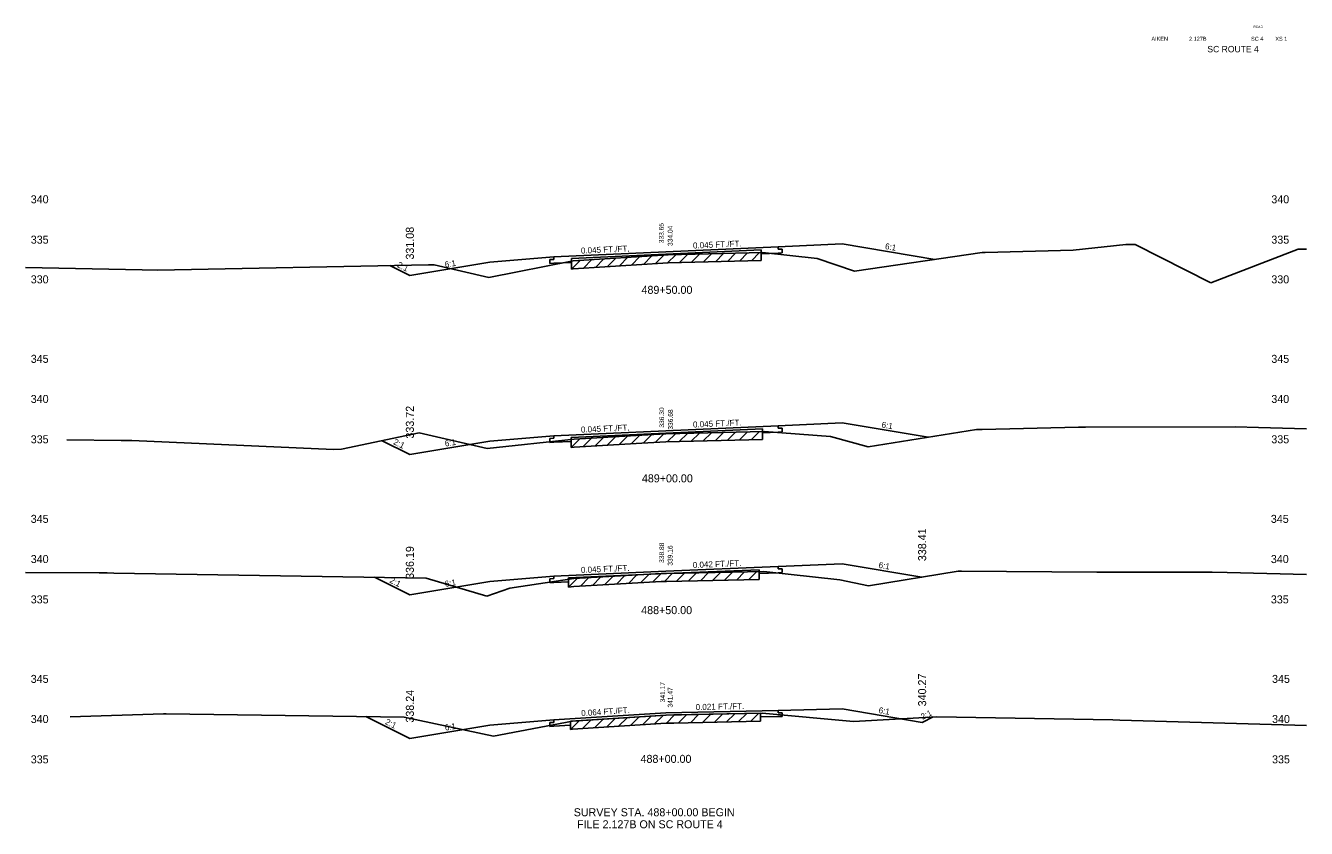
# Model space of a CAD drawing. Extents: x 883 to 1160, y 1002 to 4323.
# Drawn here: x 1000 to 1160, y 1002 to 1102.3 of the extents above; entities that cross this region are included whole.
import ezdxf

# ---------------------------------------------------------------- set-up
doc = ezdxf.new("R2010")
doc.units = 0
for name, color, linetype in [('Level 1', 7, 'Continuous'), ('Level 10', 7, 'Continuous'), ('Level 11', 7, 'Continuous'), ('Level 12', 7, 'Continuous'), ('Level 3', 7, 'Continuous'), ('Level 32', 7, 'Continuous'), ('Level 33', 7, 'Continuous'), ('Level 53', 7, 'Continuous'), ('Level 59', 7, 'Continuous'), ('Level 6', 7, 'Continuous'), ('Level 60', 7, 'Continuous'), ('Level 61', 7, 'Continuous'), ('Level 7', 7, 'Continuous')]:
    doc.layers.add(name, color=color, linetype=linetype)

msp = doc.modelspace()

# ---------------------------------------------------------------- linework, layer by layer
at = {"layer": 'Level 11'}
for p, q in [((1094, 1074.37), (1094, 1074.67)), ((1094.5, 1074.4), (1094, 1074.37)), ((1094, 1073.89), (1094.5, 1073.92)), ((1094.5, 1073.92), (1094.5, 1074.4)), ((1066, 1073.11), (1065.5, 1073.09)), ((1065.5, 1073.09), (1065.5, 1072.61)), ((1065.5, 1072.61), (1066, 1072.63)), ((1066, 1073.41), (1066, 1073.11)), ((1094, 1052.01), (1094, 1052.31)), ((1094.5, 1052.03), (1094, 1052.01)), ((1094, 1051.53), (1094.5, 1051.55)), ((1094.5, 1051.55), (1094.5, 1052.03)), ((1066, 1050.75), (1065.5, 1050.73)), ((1065.5, 1050.73), (1065.5, 1050.25)), ((1065.5, 1050.25), (1066, 1050.27)), ((1066, 1051.05), (1066, 1050.75)), ((1094, 1034.44), (1094, 1034.74)), ((1094.5, 1034.46), (1094, 1034.44)), ((1094, 1033.96), (1094.5, 1033.98)), ((1094.5, 1033.98), (1094.5, 1034.46)), ((1066, 1033.23), (1065.5, 1033.21)), ((1065.5, 1033.21), (1065.5, 1032.73)), ((1065.5, 1032.73), (1066, 1032.75)), ((1066, 1033.53), (1066, 1033.23)), ((1094, 1016.47), (1094, 1016.77)), ((1094.5, 1016.48), (1094, 1016.47)), ((1094.5, 1016), (1094.5, 1016.48)), ((1066, 1015.27), (1065.5, 1015.24)), ((1065.5, 1015.24), (1065.5, 1014.76)), ((1065.5, 1014.76), (1066, 1014.79)), ((1066, 1015.57), (1066, 1015.27)), ((1094, 1015.99), (1094.5, 1016))]:
    msp.add_line(p, q, dxfattribs=at)
at = {"layer": 'Level 12'}
for p, q in [((1091.9, 1073.95), (1091.9, 1073.8)), ((1091.9, 1073.8), (1094, 1073.89)), ((1068.18, 1072.73), (1066, 1072.63)), ((1068.18, 1072.88), (1068.18, 1072.73)), ((1092.07, 1051.6), (1092.07, 1051.45)), ((1092.07, 1051.45), (1094, 1051.53)), ((1068.14, 1050.37), (1066, 1050.27)), ((1068.14, 1050.62), (1068.14, 1050.37)), ((1091.64, 1034.1), (1091.64, 1033.86)), ((1091.64, 1033.86), (1094, 1033.96)), ((1067.8, 1032.83), (1066, 1032.75)), ((1067.8, 1033.14), (1067.8, 1032.83)), ((1091.8, 1016.42), (1091.8, 1015.94)), ((1068.06, 1014.92), (1066, 1014.79)), ((1068.06, 1015.37), (1068.06, 1014.92)), ((1091.8, 1015.94), (1094, 1015.99))]:
    msp.add_line(p, q, dxfattribs=at)
at = {"layer": 'Level 53'}
for p, q in [((1080, 1073.74), (1068.18, 1073.21)), ((1080, 1073.74), (1091.9, 1074.28)), ((1091.9, 1074.28), (1091.9, 1073.95)), ((1068.18, 1073.21), (1068.18, 1072.88)), ((1080, 1051.38), (1068.14, 1050.85)), ((1080, 1051.38), (1092.07, 1051.93)), ((1092.07, 1051.93), (1092.07, 1051.6)), ((1068.14, 1050.85), (1068.14, 1050.62)), ((1080, 1033.86), (1067.8, 1033.31)), ((1080, 1033.86), (1091.64, 1034.34)), ((1091.64, 1034.34), (1091.64, 1034.1)), ((1067.8, 1033.31), (1067.8, 1033.14)), ((1080, 1016.17), (1068.06, 1015.4)), ((1080, 1016.17), (1091.8, 1016.42)), ((1091.8, 1016.42), (1091.8, 1016.42)), ((1068.06, 1015.4), (1068.06, 1015.37))]:
    msp.add_line(p, q, dxfattribs=at)
at = {"layer": 'Level 59'}
for p, q in [((1066, 1073.41), (1080, 1074.04)), ((1080, 1074.04), (1094, 1074.67)), ((1066, 1051.05), (1080, 1051.68)), ((1080, 1051.68), (1094, 1052.31)), ((1066, 1033.53), (1080, 1034.16)), ((1080, 1034.16), (1094, 1034.74)), ((1066, 1015.57), (1080, 1016.47)), ((1080, 1016.47), (1094, 1016.77))]:
    msp.add_line(p, q, dxfattribs=at)
at = {"layer": 'Level 6'}
for p, q in [((1094, 1074.67), (1102, 1075.03)), ((1058, 1072.75), (1066, 1073.41)), ((1094, 1052.31), (1102, 1052.67)), ((1058, 1050.39), (1066, 1051.05)), ((1094, 1034.74), (1102, 1035.08)), ((1058, 1032.86), (1066, 1033.53)), ((1094, 1016.77), (1102, 1016.94)), ((1058, 1014.9), (1066, 1015.57))]:
    msp.add_line(p, q, dxfattribs=at)
at = {"layer": 'Level 60'}
for p, q in [((1068.41, 1072.93), (1080.29, 1073.67)), ((1080.29, 1073.67), (1092.06, 1073.96)), ((1092.06, 1073.96), (1098.88, 1073.21)), ((1103.53, 1071.62), (1119.5, 1073.97)), ((1119.5, 1073.97), (1119.88, 1073.98)), ((1119.88, 1073.98), (1130.88, 1074.27)), ((1130.88, 1074.27), (1137.46, 1074.96)), ((1137.46, 1074.96), (1138.63, 1074.96)), ((1138.63, 1074.96), (1148.06, 1070.18)), ((1148.06, 1070.18), (1158.99, 1074.39)), ((1158.99, 1074.39), (1160, 1074.36)), ((1000, 1072.07), (1014.57, 1071.79)), ((1016.48, 1071.76), (1050.35, 1072.42)), ((1050.35, 1072.42), (1051.02, 1072.42)), ((1051.02, 1072.42), (1057.88, 1070.83)), ((1057.88, 1070.83), (1068.41, 1072.93)), ((1098.88, 1073.21), (1103.53, 1071.62)), ((1014.57, 1071.79), (1016.48, 1071.76)), ((1039.46, 1049.38), (1049.17, 1051.44)), ((1049.17, 1051.44), (1057.66, 1049.49)), ((1076.98, 1051.13), (1080, 1051.3)), ((1080, 1051.3), (1092.26, 1051.61)), ((1092.26, 1051.61), (1100.56, 1050.99)), ((1105.24, 1049.67), (1118.81, 1051.87)), ((1118.81, 1051.87), (1119.51, 1051.86)), ((1119.51, 1051.86), (1131.54, 1052.15)), ((1131.54, 1052.15), (1132.39, 1052.15)), ((1132.39, 1052.15), (1151.14, 1052.2)), ((1151.14, 1052.2), (1154, 1052.12)), ((1154, 1052.12), (1160, 1051.93)), ((1005.15, 1050.56), (1011.95, 1050.48)), ((1011.95, 1050.48), (1013.27, 1050.46)), ((1013.27, 1050.46), (1038.46, 1049.36)), ((1057.66, 1049.49), (1068.54, 1050.66)), ((1068.54, 1050.66), (1076.98, 1051.13)), ((1100.56, 1050.99), (1105.24, 1049.67)), ((1038.46, 1049.36), (1039.46, 1049.38)), ((1000, 1034), (1009.19, 1033.94)), ((1009.19, 1033.94), (1010.17, 1033.93)), ((1010.17, 1033.93), (1011, 1033.89)), ((1011, 1033.89), (1050.05, 1033.3)), ((1068.49, 1033.25), (1079.41, 1033.85)), ((1079.41, 1033.85), (1080.05, 1033.88)), ((1080.05, 1033.88), (1092.22, 1034.11)), ((1092.22, 1034.11), (1101.71, 1033.07)), ((1105.31, 1032.33), (1116.48, 1034.17)), ((1116.48, 1034.17), (1116.92, 1034.16)), ((1116.92, 1034.16), (1133.84, 1034.04)), ((1133.84, 1034.04), (1148.22, 1034.05)), ((1148.22, 1034.05), (1150.1, 1034)), ((1150.1, 1034), (1160, 1033.73)), ((1050.05, 1033.3), (1057.63, 1031.04)), ((1057.63, 1031.04), (1060.51, 1032.02)), ((1060.51, 1032.02), (1068.49, 1033.25)), ((1101.71, 1033.07), (1105.31, 1032.33)), ((1005.55, 1015.94), (1017.22, 1016.32)), ((1017.22, 1016.32), (1017.55, 1016.32)), ((1017.55, 1016.32), (1047.3, 1015.92)), ((1068.32, 1015.41), (1080.04, 1016.17)), ((1080.04, 1016.17), (1080.96, 1016.19)), ((1080.96, 1016.19), (1092.01, 1016.42)), ((1092.01, 1016.42), (1103.44, 1015.36)), ((1047.3, 1015.92), (1058.43, 1013.56)), ((1058.43, 1013.56), (1068.32, 1015.41)), ((1103.44, 1015.36), (1113.84, 1015.98)), ((1113.84, 1015.98), (1135.82, 1015.57)), ((1135.82, 1015.57), (1136.7, 1015.53)), ((1136.7, 1015.53), (1160, 1014.87))]:
    msp.add_line(p, q, dxfattribs=at)
at = {"layer": 'Level 61'}
for p, q in [((1079.74, 1073.64), (1078.68, 1072.57)), ((1081.21, 1073.69), (1080.18, 1072.66)), ((1082.7, 1073.73), (1081.68, 1072.7)), ((1084.2, 1073.77), (1083.18, 1072.74)), ((1085.7, 1073.8), (1084.68, 1072.78)), ((1087.2, 1073.84), (1086.18, 1072.81)), ((1088.7, 1073.88), (1087.68, 1072.85)), ((1090.2, 1073.91), (1089.18, 1072.89)), ((1091.7, 1073.95), (1090.68, 1072.92)), ((1091.9, 1072.95), (1091.9, 1073.95)), ((1069.28, 1072.98), (1068.18, 1071.88)), ((1068.18, 1072.88), (1068.18, 1071.88)), ((1068.41, 1071.93), (1080.29, 1072.67)), ((1070.74, 1073.08), (1069.68, 1072.01)), ((1072.24, 1073.17), (1071.18, 1072.1)), ((1073.74, 1073.26), (1072.68, 1072.2)), ((1075.24, 1073.36), (1074.18, 1072.29)), ((1076.74, 1073.45), (1075.68, 1072.38)), ((1078.24, 1073.54), (1077.18, 1072.48)), ((1080.29, 1072.67), (1091.9, 1072.95)), ((1068.18, 1071.88), (1068.41, 1071.93)), ((1079.7, 1051.28), (1078.64, 1050.22)), ((1081.17, 1051.33), (1080.14, 1050.3)), ((1082.67, 1051.37), (1081.64, 1050.34)), ((1084.17, 1051.4), (1083.14, 1050.38)), ((1085.67, 1051.44), (1084.64, 1050.42)), ((1087.17, 1051.48), (1086.14, 1050.45)), ((1088.67, 1051.52), (1087.64, 1050.49)), ((1090.17, 1051.56), (1089.14, 1050.53)), ((1091.67, 1051.59), (1090.64, 1050.57)), ((1092.07, 1050.6), (1092.07, 1051.6)), ((1069.22, 1050.7), (1068.14, 1049.62)), ((1068.14, 1050.62), (1068.14, 1049.62)), ((1068.14, 1049.62), (1068.54, 1049.66)), ((1068.54, 1049.66), (1076.98, 1050.13)), ((1070.7, 1050.78), (1069.64, 1049.72)), ((1072.2, 1050.86), (1071.14, 1049.81)), ((1073.7, 1050.95), (1072.64, 1049.89)), ((1075.2, 1051.03), (1074.14, 1049.97)), ((1076.7, 1051.12), (1075.64, 1050.06)), ((1076.98, 1050.13), (1080, 1050.3)), ((1078.2, 1051.2), (1077.14, 1050.14)), ((1080, 1050.3), (1092.07, 1050.6)), ((1076.36, 1033.68), (1075.3, 1032.62)), ((1077.86, 1033.76), (1076.8, 1032.7)), ((1079.36, 1033.84), (1078.3, 1032.79)), ((1080.83, 1033.9), (1079.8, 1032.87)), ((1082.32, 1033.92), (1081.3, 1032.9)), ((1083.82, 1033.95), (1082.8, 1032.93)), ((1085.32, 1033.98), (1084.3, 1032.96)), ((1086.82, 1034.01), (1085.8, 1032.99)), ((1088.32, 1034.03), (1087.3, 1033.02)), ((1089.82, 1034.06), (1088.8, 1033.04)), ((1091.32, 1034.09), (1090.3, 1033.07)), ((1091.64, 1033.1), (1091.64, 1034.1)), ((1068.93, 1033.27), (1067.8, 1032.14)), ((1067.8, 1033.14), (1067.8, 1032.14)), ((1067.8, 1032.14), (1068.49, 1032.25)), ((1068.49, 1032.25), (1079.41, 1032.85)), ((1070.36, 1033.35), (1069.3, 1032.29)), ((1071.86, 1033.43), (1070.8, 1032.37)), ((1073.36, 1033.51), (1072.3, 1032.46)), ((1074.86, 1033.6), (1073.8, 1032.54)), ((1079.41, 1032.85), (1080.05, 1032.88)), ((1080.05, 1032.88), (1091.64, 1033.1)), ((1078.13, 1016.05), (1077.06, 1014.98)), ((1079.63, 1016.14), (1078.56, 1015.07)), ((1081.08, 1016.19), (1080.06, 1015.17)), ((1082.58, 1016.22), (1081.56, 1015.2)), ((1084.08, 1016.25), (1083.06, 1015.23)), ((1085.58, 1016.29), (1084.56, 1015.26)), ((1087.08, 1016.32), (1086.06, 1015.3)), ((1088.58, 1016.35), (1087.56, 1015.33)), ((1090.08, 1016.38), (1089.06, 1015.36)), ((1091.58, 1016.41), (1090.56, 1015.39)), ((1091.8, 1015.42), (1091.8, 1016.42)), ((1069.16, 1015.47), (1068.06, 1014.37)), ((1068.06, 1015.37), (1068.06, 1014.37)), ((1068.06, 1014.37), (1068.32, 1014.41)), ((1068.32, 1014.41), (1080.04, 1015.17)), ((1070.63, 1015.56), (1069.56, 1014.49)), ((1072.13, 1015.66), (1071.06, 1014.59)), ((1073.63, 1015.76), (1072.56, 1014.69)), ((1075.13, 1015.85), (1074.06, 1014.78)), ((1076.63, 1015.95), (1075.56, 1014.88)), ((1080.04, 1015.17), (1080.96, 1015.19)), ((1080.96, 1015.19), (1091.8, 1015.42))]:
    msp.add_line(p, q, dxfattribs=at)
at = {"layer": 'Level 7'}
for p, q in [((1102, 1075.03), (1113.6, 1073.1)), ((1045.5, 1072.33), (1048, 1071.08)), ((1048, 1071.08), (1058, 1072.75)), ((1102, 1052.67), (1112.74, 1050.88)), ((1044.53, 1050.45), (1048, 1048.72)), ((1048, 1048.72), (1058, 1050.39)), ((1102, 1035.08), (1111.94, 1033.42)), ((1043.59, 1033.4), (1048, 1031.19)), ((1048, 1031.19), (1058, 1032.86)), ((1102, 1016.94), (1112, 1015.27)), ((1042.5, 1015.99), (1048, 1013.24)), ((1048, 1013.24), (1058, 1014.9)), ((1112, 1015.27), (1113.37, 1015.95))]:
    msp.add_line(p, q, dxfattribs=at)

# ---------------------------------------------------------------- texts
at = {"layer": 'Level 1'}
for s, height, p in [('AIKEN', 0.5, (1140.64, 1100.41)), (' 2.127B', 0.5, (1145.15, 1100.41)), ('SC 4', 0.5, (1153.09, 1100.41)), ('XS 1', 0.5, (1156.12, 1100.41)), ('SC ROUTE 4', 0.8, (1147.63, 1098.97)), ('489+50.00', 1, (1076.94, 1068.8)), ('489+00.00', 1, (1076.99, 1045.25)), ('488+50.00', 1, (1076.9, 1028.79)), ('488+00.00', 1, (1076.82, 1010.21)), ('SURVEY STA. 488+00.00 BEGIN', 1, (1068.47, 1003.54)), ('FILE 2.127B ON SC ROUTE 4 ', 1, (1068.88, 1002.04))]:
    msp.add_text(s, height=height, dxfattribs=at).set_placement(p)
at = {"layer": 'Level 10'}
for s, p in [('333.65', (1079.72, 1075.12)), ('336.30', (1079.76, 1052.08)), ('338.88', (1079.76, 1035.19)), ('341.17', (1079.88, 1017.77))]:
    msp.add_text(s, height=0.6, rotation=90, dxfattribs=at).set_placement(p)
at = {"layer": 'Level 3'}
for s, height, p in [('ROAD', 0.3, (1153.38, 1102)), (' 340', 1, (1000.27, 1080.11)), (' 340', 1, (1155.25, 1080.11)), (' 335', 1, (1000.27, 1075.07)), (' 335', 1, (1155.25, 1075.07)), (' 330', 1, (1000.27, 1070.11)), (' 330', 1, (1155.25, 1070.11)), (' 345', 1, (1000.27, 1060.18)), (' 345', 1, (1155.25, 1060.18)), (' 340', 1, (1000.27, 1055.17)), (' 340', 1, (1155.25, 1055.17)), (' 335', 1, (1000.27, 1050.13)), (' 335', 1, (1155.25, 1050.13)), (' 345', 1, (1000.27, 1040.19)), (' 345', 1, (1155.19, 1040.19)), (' 340', 1, (1000.27, 1035.17)), (' 340', 1, (1155.19, 1035.17)), (' 335', 1, (1000.27, 1030.13)), (' 335', 1, (1155.19, 1030.13)), (' 345', 1, (1000.27, 1020.2)), (' 345', 1, (1155.34, 1020.2)), (' 340', 1, (1000.27, 1015.19)), (' 340', 1, (1155.34, 1015.19)), (' 335', 1, (1000.27, 1010.15)), (' 335', 1, (1155.34, 1010.15))]:
    msp.add_text(s, height=height, dxfattribs=at).set_placement(p)
at = {"layer": 'Level 32'}
for s, rotation, p in [('0.045 FT./FT.', 2.5766, (1083.39, 1074.45)), ('0.045 FT./FT.', 2.5766, (1069.39, 1073.82)), ('6:1', 350.5377, (1107.32, 1074.4)), ('2:1', 333.435, (1046.35, 1072.18)), ('6:1', 9.4623, (1052.43, 1072.07)), ('0.045 FT./FT.', 2.5766, (1083.39, 1052.09)), ('6:1', 350.5377, (1106.89, 1052.11)), ('0.045 FT./FT.', 2.5766, (1069.39, 1051.46)), ('2:1', 333.435, (1045.87, 1050.06)), ('6:1', 9.4623, (1052.43, 1049.71)), ('0.042 FT./FT.', 2.3888, (1083.36, 1034.55)), ('6:1', 350.5377, (1106.52, 1034.58)), ('0.045 FT./FT.', 2.5766, (1069.39, 1033.93)), ('2:1', 333.435, (1045.4, 1032.77)), ('6:1', 9.4623, (1052.43, 1032.19)), ('0.021 FT./FT.', 1.2145, (1083.71, 1016.8)), ('0.064 FT./FT.', 3.6848, (1069.43, 1016.04)), ('6:1', 350.5377, (1106.52, 1016.44)), ('2:1', 26.5651, (1112.06, 1015.58)), ('2:1', 333.435, (1044.85, 1015.09)), ('6:1', 9.4623, (1052.43, 1014.23))]:
    msp.add_text(s, height=0.75, rotation=rotation, dxfattribs=at).set_placement(p)
at = {"layer": 'Level 33'}
for s, p in [('331.08', (1048.5, 1073.08)), ('333.72', (1048.5, 1050.72)), ('338.41', (1112.5, 1035.41)), ('336.19', (1048.5, 1033.19)), ('340.27', (1112.5, 1017.27)), ('338.24', (1048.5, 1015.24))]:
    msp.add_text(s, height=1, rotation=90, dxfattribs=at).set_placement(p)
at = {"layer": 'Level 59'}
for s, p in [(' 334.04', (1080.82, 1074.54)), (' 336.68', (1080.86, 1051.6)), (' 339.16', (1080.82, 1034.61)), (' 341.47', (1080.82, 1016.89))]:
    msp.add_text(s, height=0.6, rotation=90, dxfattribs=at).set_placement(p)

doc.saveas('drawing.dxf')
